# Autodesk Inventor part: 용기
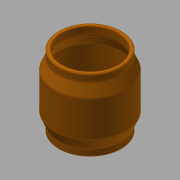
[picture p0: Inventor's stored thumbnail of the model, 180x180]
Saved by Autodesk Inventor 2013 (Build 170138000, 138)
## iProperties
Created: 2018-01
Part Number: 용기
Material: ABS 플라스틱
Document SubType Name: Modeling
Designer: mduedu
Density: 1 g/cm^3
Author: mduedu
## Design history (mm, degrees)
sketch "스케치1"
  geometry: L1 (0, 0)-(-35, 0); L2 (-35, 0)-(-35, 8); L3 (-35, 8)-(-40, 20); L4 (-40, 20)-(-40, 60); L5 (-40, 60)-(-35, 72); L6 (-35, 72)-(-35, 80); L7 (-35, 80)-(0, 80); L8 (0, 80)-(0, 0)
  constraints: 16 end point, 3 collinear, 3 parallel, 1 horizontal, 1 perpendicular
  dimensions: "d0" = 8 distance of L1.end L2.end; "d2" = 70 diameter of L2 L8; "d3" = 20 distance from line of L3.end L1; "d4" = 60 distance from line of L4.end L1; "d5" = 20 distance from line of L4.end L7; "d6" = 80 diameter of L4 L8
revolve "회전1" sketch "스케치1" stored, may be unused: angle "d7" = 90 deg
fillet "모깎기1" dims "d8" = 3
feature "쉘1" dims "d9" = 4
fillet "모깎기2" dims "d10" = 1
chamfer "모따기1" distance "d11" = 0.5; stored, may be unused: second distance "d12" = 2, angle "d13" = 45 deg
node "솔리드1"
